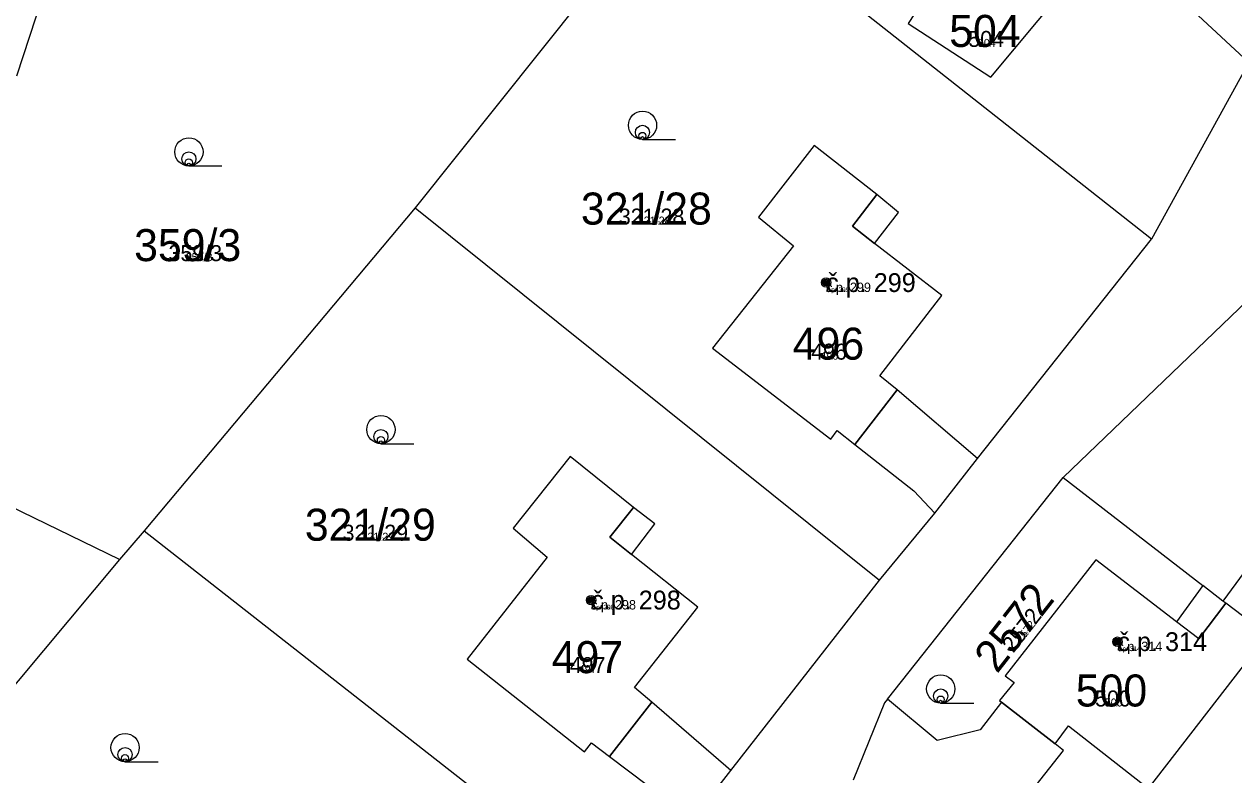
# Model space of a CAD drawing. Extents: x -744652 to -739090, y -980828 to -975855.
# Drawn here: x -742351.9 to -742287.7, y -978981.6 to -978941.8 of the extents above; entities that cross this region are included whole.
import ezdxf

# ---------------------------------------------------------------- set-up
doc = ezdxf.new("R2010")
doc.units = 0
for name, color, linetype in [('KAT_02_hranice parcel', 7, 'Continuous'), ('KAT_03_1000_st čísla parcelní', 7, 'Continuous'), ('KAT_03_1000_čísla parcelní', 7, 'Continuous'), ('KAT_03_1000_čísla popisná', 7, 'Continuous'), ('KAT_03_100_st čísla parcelní', 7, 'Continuous'), ('KAT_03_100_čísla parcelní', 7, 'Continuous'), ('KAT_03_100_čísla popisná', 7, 'Continuous'), ('KAT_03_250_st čísla parcelní', 7, 'Continuous'), ('KAT_03_250_čísla parcelní', 7, 'Continuous'), ('KAT_03_250_čísla popisná', 7, 'Continuous'), ('KAT_03_500_st čísla parcelní', 7, 'Continuous'), ('KAT_03_500_čísla parcelní', 7, 'Continuous'), ('KAT_03_500_čísla popisná', 7, 'Continuous'), ('KAT_04_vnitřní kresba', 7, 'Continuous'), ('KAT_05_1000_značky kultur', 7, 'Continuous'), ('KAT_05_100_značky kultur', 7, 'Continuous'), ('KAT_05_250_značky kultur', 7, 'Continuous'), ('KAT_05_500_značky kultur', 7, 'Continuous'), ('KAT_07_1000_značky budov', 7, 'Continuous'), ('KAT_07_100_značky budov', 7, 'Continuous'), ('KAT_07_500_značky budov', 7, 'Continuous'), ('KAT_14_plocha_budovy', 7, 'Continuous')]:
    doc.layers.add(name, color=color, linetype=linetype)

msp = doc.modelspace()

# ---------------------------------------------------------------- linework, layer by layer
at = {"layer": 'KAT_02_hranice parcel'}
for p, q in [((-742352.31, -978944.52), (-742348.59, -978933.15)), ((-742292.06, -978953.18), (-742316.93, -978933.58)), ((-742321.71, -978939.68), (-742331.15, -978951.52)), ((-742331.15, -978951.52), (-742345.55, -978968.67)), ((-742331.15, -978951.52), (-742306.49, -978971.29)), ((-742301.3, -978964.83), (-742292.06, -978953.18)), ((-742346.86, -978970.19), (-742358.65, -978964.45)), ((-742303.55, -978967.72), (-742301.3, -978964.83)), ((-742306.08, -978977.6), (-742296.74, -978965.84)), ((-742296.74, -978965.84), (-742289.33, -978971.57)), ((-742306.49, -978971.29), (-742303.55, -978967.72)), ((-742345.55, -978968.67), (-742346.86, -978970.19)), ((-742345.55, -978968.67), (-742320.15, -978988.53)), ((-742314.39, -978981.39), (-742306.49, -978971.29)), ((-742288.26, -978972.4), (-742289.33, -978971.57)), ((-742316.66, -978984.28), (-742314.39, -978981.39))]:
    msp.add_line(p, q, dxfattribs=at)
for points in [[(-742308.88, -978923.38), (-742286.88, -978943.81), (-742292.06, -978953.18)], [(-742296.82, -978940.05), (-742301.75, -978936.8), (-742304.97, -978941.74), (-742300.58, -978944.58), (-742296.82, -978940.05)], [(-742301.3, -978964.83), (-742305.55, -978961.19), (-742306.48, -978960.44), (-742303.18, -978956.18), (-742306.76, -978953.41), (-742305.49, -978951.77), (-742306.63, -978950.82), (-742309.96, -978948.21), (-742312.93, -978952.01), (-742311.07, -978953.53), (-742315.36, -978958.97), (-742309.09, -978963.8), (-742308.74, -978963.34), (-742307.81, -978964.09), (-742304.67, -978966.54), (-742303.55, -978967.72)], [(-742296.74, -978965.84), (-742286.06, -978955.59), (-742281.9, -978954.58), (-742278.45, -978956.27), (-742262.77, -978977.93)], [(-742314.39, -978981.39), (-742318.58, -978977.76), (-742319.51, -978976.99), (-742316.15, -978972.71), (-742319.66, -978969.93), (-742318.42, -978968.3), (-742319.57, -978967.42), (-742322.92, -978964.72), (-742325.95, -978968.52), (-742324.15, -978970.06), (-742328.39, -978975.48), (-742322.17, -978980.39), (-742321.8, -978979.91), (-742320.84, -978980.64), (-742317.81, -978982.92), (-742316.66, -978984.28)], [(-742264.29, -978979.72), (-742285.8, -978969.05), (-742288.26, -978972.4)], [(-742346.86, -978970.19), (-742353.6, -978978.24), (-742358.86, -978985.4)], [(-742289.33, -978971.57), (-742290.73, -978973.5), (-742295.01, -978970.21), (-742299.83, -978976.36), (-742299.34, -978976.72), (-742300.12, -978977.68), (-742300.01, -978977.76), (-742301.15, -978979.23), (-742303.44, -978979.8), (-742306.08, -978977.6)], [(-742299.44, -978983.76), (-742296.73, -978980.32), (-742297.16, -978979.98), (-742296.46, -978979.01), (-742292.21, -978982.34), (-742285.89, -978974.18), (-742288.11, -978972.5), (-742288.26, -978972.4)], [(-742306.08, -978977.6), (-742306.23, -978977.79), (-742307.89, -978981.9)]]:
    msp.add_lwpolyline(points, dxfattribs=at)
at = {"layer": 'KAT_03_1000_čísla popisná'}
for centre in [(-742309.33, -978955.49), (-742309.33, -978955.49), (-742321.81, -978972.34), (-742321.81, -978972.34), (-742293.86, -978974.55), (-742293.86, -978974.55)]:
    msp.add_circle(centre, 0.25, dxfattribs=at)
at = {"layer": 'KAT_03_100_čísla popisná'}
for centre in [(-742309.33, -978955.49), (-742309.33, -978955.49), (-742321.81, -978972.34), (-742321.81, -978972.34), (-742293.86, -978974.55), (-742293.86, -978974.55)]:
    msp.add_circle(centre, 0.025, dxfattribs=at)
at = {"layer": 'KAT_03_250_čísla popisná'}
for centre in [(-742309.33, -978955.49), (-742309.33, -978955.49), (-742321.81, -978972.34), (-742321.81, -978972.34), (-742293.86, -978974.55), (-742293.86, -978974.55)]:
    msp.add_circle(centre, 0.0625, dxfattribs=at)
at = {"layer": 'KAT_03_500_čísla popisná'}
for centre in [(-742309.33, -978955.49), (-742309.33, -978955.49), (-742321.81, -978972.34), (-742321.81, -978972.34), (-742293.86, -978974.55), (-742293.86, -978974.55)]:
    msp.add_circle(centre, 0.125, dxfattribs=at)
at = {"layer": 'KAT_04_vnitřní kresba'}
for p, q in [((-742306.63, -978950.82), (-742307.93, -978952.49)), ((-742307.93, -978952.49), (-742306.76, -978953.41)), ((-742305.55, -978961.19), (-742307.81, -978964.09)), ((-742319.57, -978967.42), (-742320.81, -978969.01)), ((-742320.81, -978969.01), (-742319.66, -978969.93)), ((-742289.54, -978974.39), (-742288.11, -978972.5)), ((-742289.54, -978974.39), (-742290.73, -978973.5)), ((-742318.58, -978977.76), (-742320.84, -978980.64)), ((-742297.16, -978979.98), (-742300.01, -978977.76))]:
    msp.add_line(p, q, dxfattribs=at)
at = {"layer": 'KAT_05_1000_značky kultur'}
for p, q in [((-742319.083, -978947.89), (-742317.333, -978947.89)), ((-742343.173, -978949.3), (-742341.423, -978949.3)), ((-742332.973, -978964.04), (-742331.223, -978964.04)), ((-742303.243, -978977.81), (-742301.493, -978977.81)), ((-742346.563, -978980.92), (-742344.813, -978980.92))]:
    msp.add_line(p, q, dxfattribs=at)
for centre in [(-742319.083, -978947.14), (-742343.173, -978948.55), (-742332.973, -978963.29), (-742303.243, -978977.06), (-742346.563, -978980.17)]:
    msp.add_circle(centre, 0.75, dxfattribs=at)
at = {"layer": 'KAT_05_100_značky kultur'}
for p, q in [((-742319.089, -978947.89), (-742318.914, -978947.89)), ((-742343.179, -978949.3), (-742343.004, -978949.3)), ((-742332.979, -978964.04), (-742332.804, -978964.04)), ((-742303.249, -978977.81), (-742303.074, -978977.81)), ((-742346.569, -978980.92), (-742346.394, -978980.92))]:
    msp.add_line(p, q, dxfattribs=at)
for centre in [(-742319.089, -978947.815), (-742343.179, -978949.225), (-742332.979, -978963.965), (-742303.249, -978977.735), (-742346.569, -978980.845)]:
    msp.add_circle(centre, 0.075, dxfattribs=at)
at = {"layer": 'KAT_05_250_značky kultur'}
for p, q in [((-742319.088, -978947.89), (-742318.651, -978947.89)), ((-742343.178, -978949.3), (-742342.741, -978949.3)), ((-742332.978, -978964.04), (-742332.541, -978964.04)), ((-742303.248, -978977.81), (-742302.811, -978977.81)), ((-742346.568, -978980.92), (-742346.131, -978980.92))]:
    msp.add_line(p, q, dxfattribs=at)
for centre in [(-742319.088, -978947.702), (-742343.178, -978949.112), (-742332.978, -978963.852), (-742303.248, -978977.622), (-742346.568, -978980.732)]:
    msp.add_circle(centre, 0.187, dxfattribs=at)
at = {"layer": 'KAT_05_500_značky kultur'}
for p, q in [((-742319.086, -978947.89), (-742318.211, -978947.89)), ((-742343.177, -978949.3), (-742342.302, -978949.3)), ((-742332.976, -978964.04), (-742332.101, -978964.04)), ((-742303.247, -978977.81), (-742302.372, -978977.81)), ((-742346.567, -978980.92), (-742345.692, -978980.92))]:
    msp.add_line(p, q, dxfattribs=at)
for centre in [(-742319.086, -978947.515), (-742343.176, -978948.925), (-742332.976, -978963.665), (-742303.246, -978977.435), (-742346.566, -978980.545)]:
    msp.add_circle(centre, 0.375, dxfattribs=at)
at = {"layer": 'KAT_07_1000_značky budov'}
for centre in [(-742309.337, -978955.489), (-742321.817, -978972.339), (-742293.867, -978974.549)]:
    msp.add_circle(centre, 0.175, dxfattribs=at)
at = {"layer": 'KAT_07_100_značky budov'}
for centre in [(-742309.331, -978955.49), (-742321.811, -978972.34), (-742293.861, -978974.55)]:
    msp.add_circle(centre, 0.0175, dxfattribs=at)
at = {"layer": 'KAT_07_500_značky budov'}
for centre, radius in [((-742309.333, -978955.49), 0.0875), ((-742309.332, -978955.49), 0.0438), ((-742321.813, -978972.34), 0.0875), ((-742321.812, -978972.34), 0.0438), ((-742293.863, -978974.55), 0.0875), ((-742293.862, -978974.55), 0.0438)]:
    msp.add_circle(centre, radius, dxfattribs=at)
at = {"layer": 'KAT_14_plocha_budovy'}
for points in [[(-742308.74, -978963.34), (-742307.81, -978964.09), (-742305.55, -978961.19), (-742306.48, -978960.44), (-742303.18, -978956.18), (-742306.76, -978953.41), (-742307.93, -978952.49), (-742306.63, -978950.82), (-742309.96, -978948.21), (-742312.93, -978952.01), (-742311.07, -978953.53), (-742315.36, -978958.97), (-742309.09, -978963.8)], [(-742324.15, -978970.06), (-742328.39, -978975.48), (-742322.17, -978980.39), (-742321.8, -978979.91), (-742320.84, -978980.64), (-742318.58, -978977.76), (-742319.51, -978976.99), (-742316.15, -978972.71), (-742319.66, -978969.93), (-742320.81, -978969.01), (-742319.57, -978967.42), (-742322.92, -978964.72), (-742325.95, -978968.52)], [(-742300.12, -978977.68), (-742300.01, -978977.76), (-742297.16, -978979.98), (-742296.46, -978979.01), (-742292.21, -978982.34), (-742285.89, -978974.18), (-742288.11, -978972.5), (-742289.54, -978974.39), (-742290.73, -978973.5), (-742295.01, -978970.21), (-742299.83, -978976.36), (-742299.34, -978976.72)]]:
    msp.add_lwpolyline(points, close=True, dxfattribs=at)

# ---------------------------------------------------------------- texts
at = {"layer": 'KAT_03_1000_st čísla parcelní'}
for s, p in [('504', (-742302.794, -978942.98)), ('496', (-742311.104, -978959.58)), ('497', (-742323.904, -978976.22)), ('500', (-742296.074, -978977.99))]:
    msp.add_text(s, height=1.7, dxfattribs=at).set_placement(p)
at = {"layer": 'KAT_03_1000_čísla parcelní'}
for s, p in [('321/28', (-742322.355, -978952.41)), ('359/3', (-742346.083, -978954.35)), ('321/29', (-742337.015, -978969.19))]:
    msp.add_text(s, height=1.7, dxfattribs=at).set_placement(p)
msp.add_text('2572', height=1.7, rotation=52, dxfattribs=at).set_placement((-742300.253, -978976.289))
at = {"layer": 'KAT_03_1000_čísla popisná'}
for s, height, p in [('504', 0.017, (-742300.787, -978942.98)), ('č.p. 299', 1, (-742309.33, -978955.99)), ('496', 0.017, (-742309.169, -978959.58)), ('č.p. 298', 1, (-742321.81, -978972.84)), ('č.p. 314', 1, (-742293.86, -978975.05)), ('497', 0.017, (-742322.009, -978976.22)), ('500', 0.017, (-742294.04, -978977.99))]:
    msp.add_text(s, height=height, dxfattribs=at).set_placement(p)
at = {"layer": 'KAT_03_100_st čísla parcelní'}
for s, p in [('504', (-742300.969, -978942.98)), ('496', (-742309.345, -978959.58)), ('497', (-742322.181, -978976.22)), ('500', (-742294.225, -978977.99))]:
    msp.add_text(s, height=0.17, dxfattribs=at).set_placement(p)
at = {"layer": 'KAT_03_100_čísla parcelní'}
for s, p in [('321/28', (-742318.729, -978952.41)), ('359/3', (-742342.794, -978954.35)), ('321/29', (-742333.407, -978969.19))]:
    msp.add_text(s, height=0.17, dxfattribs=at).set_placement(p)
msp.add_text('2572', height=0.17, rotation=52, dxfattribs=at).set_placement((-742298.703, -978974.305))
at = {"layer": 'KAT_03_100_čísla popisná'}
for s, height, p in [('504', 0.0017, (-742300.768, -978942.98)), ('č.p. 299', 0.1, (-742309.33, -978955.99)), ('496', 0.0017, (-742309.152, -978959.58)), ('č.p. 298', 0.1, (-742321.81, -978972.84)), ('č.p. 314', 0.1, (-742293.86, -978975.05)), ('497', 0.0017, (-742321.992, -978976.22)), ('500', 0.0017, (-742294.022, -978977.99))]:
    msp.add_text(s, height=height, dxfattribs=at).set_placement(p)
at = {"layer": 'KAT_03_250_st čísla parcelní'}
for s, p in [('504', (-742301.273, -978942.98)), ('496', (-742309.638, -978959.58)), ('497', (-742322.469, -978976.22)), ('500', (-742294.533, -978977.99))]:
    msp.add_text(s, height=0.425, dxfattribs=at).set_placement(p)
at = {"layer": 'KAT_03_250_čísla parcelní'}
for s, p in [('321/28', (-742319.333, -978952.41)), ('359/3', (-742343.342, -978954.35)), ('321/29', (-742334.008, -978969.19))]:
    msp.add_text(s, height=0.425, dxfattribs=at).set_placement(p)
msp.add_text('2572', height=0.425, rotation=52, dxfattribs=at).set_placement((-742298.961, -978974.636))
at = {"layer": 'KAT_03_250_čísla popisná'}
for s, height, p in [('504', 0.00425, (-742300.771, -978942.98)), ('č.p. 299', 0.25, (-742309.33, -978955.99)), ('496', 0.00425, (-742309.155, -978959.58)), ('č.p. 298', 0.25, (-742321.81, -978972.84)), ('č.p. 314', 0.25, (-742293.86, -978975.05)), ('497', 0.00425, (-742321.995, -978976.22)), ('500', 0.00425, (-742294.025, -978977.99))]:
    msp.add_text(s, height=height, dxfattribs=at).set_placement(p)
at = {"layer": 'KAT_03_500_st čísla parcelní'}
for s, p in [('504', (-742301.78, -978942.98)), ('496', (-742310.127, -978959.58)), ('497', (-742322.947, -978976.22)), ('500', (-742295.047, -978977.99))]:
    msp.add_text(s, height=0.85, dxfattribs=at).set_placement(p)
at = {"layer": 'KAT_03_500_čísla parcelní'}
for s, p in [('321/28', (-742320.341, -978952.41)), ('359/3', (-742344.256, -978954.35)), ('321/29', (-742335.011, -978969.19))]:
    msp.add_text(s, height=0.85, dxfattribs=at).set_placement(p)
msp.add_text('2572', height=0.85, rotation=52, dxfattribs=at).set_placement((-742299.392, -978975.187))
at = {"layer": 'KAT_03_500_čísla popisná'}
for s, height, p in [('504', 0.0085, (-742300.776, -978942.98)), ('č.p. 299', 0.5, (-742309.33, -978955.99)), ('496', 0.0085, (-742309.16, -978959.58)), ('č.p. 298', 0.5, (-742321.81, -978972.84)), ('č.p. 314', 0.5, (-742293.86, -978975.05)), ('497', 0.0085, (-742322, -978976.22)), ('500', 0.0085, (-742294.03, -978977.99))]:
    msp.add_text(s, height=height, dxfattribs=at).set_placement(p)

doc.saveas('drawing.dxf')
